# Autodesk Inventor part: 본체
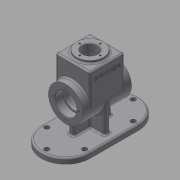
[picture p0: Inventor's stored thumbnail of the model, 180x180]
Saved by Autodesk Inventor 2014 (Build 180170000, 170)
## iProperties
Created: 2019-01
Part Number: 본체
Material: 일반
Document SubType Name: Modeling
Designer: mduedu
Density: 1 g/cm^3
Appearance: 기본값
Author: mduedu
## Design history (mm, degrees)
sketch "스케치1"
  geometry: C1 r 32 at (0, 0); 1 further point
  constraints: 1 centre point, 1 coincident
  dimensions: "d0" = 64 diameter of C1
extrude "돌출1" new body sketch "스케치1" stored distance "d1" = 90; taper "d2" = 0 deg
sketch "스케치2"
  geometry: L1 (0, 32)-(60, 32); L2 (60, 32)-(60, -32); L3 (60, -32)-(0, -32); L4 (0, -32)-(0, 32); C1 r 32 at (0, 0) reference; 2 further points
  constraints: 8 end point, 2 parallel, 1 coincident, 1 horizontal, 1 midpoint, 1 perpendicular, 1 tangent
  dimensions: "d5" = 60 distance between parallel lines of L4 L2
extrude "돌출2" join sketch "스케치2" stored distance "d7" = 64; taper "d8" = 0 deg
sketch "스케치3"
  geometry: C1 r 25 at (32, 32); 1 further point
  constraints: 1 centre point, 1 coincident
  dimensions: "d9" = 50 diameter of C1
extrude "돌출3" join sketch "스케치3" distance "d10" = 5; taper "d11" = 0 deg
sketch "스케치4"
  geometry: L1 (50, 25)-(0, 25); L2 (0, 25)-(0, -25); L3 (0, -25)-(50, -25); L4 (50, -25)-(50, 25); L5 (65, -25)-(65, 25) reference; A1 r 25 centre (0, 0) between (0, 25) and (0, -25); A2 r 25 centre (0, 0) between (0, -25) and (0, 25); 2 further points
  constraints: 8 end point, 4 point on circle, 2 centre point, 2 coincident, 2 parallel, 1 horizontal, 1 midpoint, 1 perpendicular, 1 tangent
  dimensions: "d12" = 50 diameter of A1; "d13" = 15 distance between parallel lines of L4 L5
extrude "돌출4" cut sketch "스케치4" stored distance "d14" = 48; taper "d15" = 0 deg
sketch "스케치5"
  geometry: C1 r 20 at (0, 0); 1 further point
  constraints: 1 centre point, 1 coincident
  dimensions: "d16" = 40 diameter of C1
extrude "돌출5" cut sketch "스케치5" distance "d17" = 15; taper "d18" = 0 deg
sketch "스케치6"
  geometry: C1 r 17 at (0, 0); 1 further point
  constraints: 1 centre point, 1 coincident
  dimensions: "d19" = 34 diameter of C1
extrude "돌출6" cut sketch "스케치6" stored distance "d20" = 15; taper "d21" = 0 deg
fillet "모깎기1" dims "d22" = 0.3
fillet "모깎기2" dims "d23" = 3
fillet "모깎기3" dims "d24" = 3
fillet "모깎기4" dims "d25" = 3
fillet "모깎기5" dims "d26" = 3
fillet "모깎기6" dims "d27" = 3
sketch "스케치7"
  geometry: C1 r 14 at (0, 0); 1 further point
  constraints: 1 centre point, 1 coincident
  dimensions: "d28" = 28 diameter of C1
extrude "돌출7" cut sketch "스케치7" stored distance "d29" = 15; taper "d30" = 0 deg
chamfer "모따기1" distance "d31" = 1; stored, may be unused: second distance "d32" = 2, angle "d33" = 45 deg
chamfer "모따기2" distance "d34" = 1; stored, may be unused: second distance "d35" = 2, angle "d36" = 45 deg
node "작업 평면1"
sketch "스케치8"
  geometry: L1 (45, 45)-(-45, 45); L2 (-45, 45)-(-45, -45); L3 (-45, -45)-(45, -45); L4 (45, -45)-(45, 45); L5 (45, 45)-(-45, -45); L6 (-45, 45)-(45, -45); A1 r 45 centre (45, 0) between (45, -45) and (45, 45); A2 r 45 centre (-45, 0) between (-45, 45) and (-45, -45); A3 r 45 centre (45, 0) between (0, 0) and (45, -45); A4 r 45 centre (45, 0) between (0, 0) and (0, 0); A5 r 45 centre (45, 0) between (45, 45) and (0, 0); A6 r 45 centre (-45, 0) between (0, 0) and (-45, 45); A7 r 45 centre (-45, 0) between (-45, -45) and (0, 0); 1 further point
  constraints: 14 point on circle, 12 end point, 7 centre point, 7 midpoint, 2 parallel, 1 horizontal, 1 perpendicular
  dimensions: "d99" = 90 distance between parallel lines of L1 L3; "d101" = 90 distance between parallel lines of L2 L4
extrude "돌출8" join sketch "스케치8" distance "d41" = 10; taper "d42" = 0 deg
sketch "스케치9"
  geometry: L1 (-35, 5)-(35, 5); L2 (35, 5)-(35, -5); L3 (35, -5)-(-35, -5); L4 (-35, -5)-(-35, 5); 3 further points
  constraints: 8 end point, 2 midpoint, 2 parallel, 1 horizontal, 1 horizontal alignment, 1 perpendicular, 1 vertical alignment
  dimensions: "d52" = 10 distance of L1.end L2.end; "d54" = 70 distance of L1.start L1.end
extrude "돌출9" join sketch "스케치9" stored distance "d50" = 10; taper "d51" = 0 deg
sketch "스케치10"
  geometry: L1 (0, -25)-(47, -25) reference; L2 (50, -22)-(50, -14) reference; L3 (50, -14)-(64, -14) reference; L4 (64, -14)-(65, -15) reference; L5 (65, -15)-(65, -25) reference; L6 (65, -25)-(63, -25) reference; L7 (60, -28)-(60, -29) reference; L8 (57, -32)-(0, -32) reference; L9 (-31.607, -5)-(-55, -5) reference; L10 (-55, -5)-(-55, -45) reference; L11 (-65, -45)-(-65, 45) reference; L12 (-55, 45)-(-55, 5) reference; L13 (-55, 5)-(-31.607, 5) reference; L14 (0, 32)-(57, 32) reference; L15 (60, 29)-(60, 28) reference; L16 (63, 25)-(65, 25) reference; L17 (65, 25)-(65, 15) reference; L18 (65, 15)-(64, 14) reference; L19 (64, 14)-(50, 14) reference; L20 (50, 14)-(50, 22) reference; L21 (47, 25)-(0, 25) reference; L22 (-55, -45)-(-65, -45) reference; L23 (-65, 45)-(-55, 45) reference; L24 (0, 32)-(-55, 32); A1 r 25 centre (0, 0) between (0, 25) and (0, -25) reference; A2 r 3 centre (47, -22) between (47, -25) and (50, -22) reference; A3 r 3 centre (63, -28) between (63, -25) and (60, -28) reference; A4 r 3 centre (57, -29) between (57, -32) and (60, -29) reference; A5 r 32 centre (0, 0) between (-31.607, -5) and (0, -32) reference; A6 r 32 centre (0, 0) between (0, 32) and (-31.607, 5) reference; A7 r 3 centre (57, 29) between (60, 29) and (57, 32) reference; A8 r 3 centre (63, 28) between (60, 28) and (63, 25) reference; A9 r 3 centre (47, 22) between (50, 22) and (47, 25) reference
  constraints: 2 end point, 1 perpendicular, 1 point on line, 1 tangent
feature "리브1" sketch "스케치10" dims "d57" = 1, "d58" = 10, "d59" = 0, "d60" = 0, "d61" = 1, "d62" = 1
fillet "모깎기7" dims "d63" = 3
fillet "모깎기11" dims "d102" = 3
fillet "모깎기8" dims "d64" = 3
sketch "스케치11"
  geometry: L1 (8, -29)-(8, -8) reference; L2 (-8, -8)-(-8, -29) reference; L3 (-32, -8)-(-8, -8) reference; L4 (-38, 2)-(-38, -2) reference; L5 (-8, 8)-(-32, 8) reference; L6 (-8, 29)-(-8, 8) reference; L7 (8, 8)-(8, 29) reference; L8 (32, 8)-(8, 8) reference; L9 (38, -2)-(38, 2) reference; L10 (8, -8)-(32, -8) reference; L11 (-2, -35)-(2, -35) reference; L12 (2, 35)-(-2, 35) reference; L13 (-45, -45)-(45, -45) reference; L14 (45, 45)-(-45, 45) reference; L15 (-45, -35)-(45, -35); L16 (45, 35)-(-45, 35); A1 r 6 centre (-32, -2) between (-38, -2) and (-32, -8) reference; A2 r 6 centre (-32, 2) between (-32, 8) and (-38, 2) reference; A3 r 6 centre (32, 2) between (38, 2) and (32, 8) reference; A4 r 6 centre (32, -2) between (32, -8) and (38, -2) reference; A5 r 6 centre (2, -29) between (2, -35) and (8, -29) reference; A6 r 6 centre (-2, -29) between (-8, -29) and (-2, -35) reference; A7 r 6 centre (-2, 29) between (-2, 35) and (-8, 29) reference; A8 r 6 centre (2, 29) between (8, 29) and (2, 35) reference; A9 r 45 centre (-45, 0) between (-45, 45) and (-45, -45) reference; A10 r 45 centre (45, 0) between (45, -45) and (45, 45) reference; A11 r 35 centre (-45, 0) between (-45, 35) and (-45, -35); A12 r 35 centre (45, 0) between (45, -35) and (45, 35); 7 further points
  constraints: 6 point on circle, 4 coincident, 4 end point, 2 centre point, 3 other
  dimensions: "d103" = 10 distance between parallel lines of L16 L14
hole "구멍1" sketch "스케치11" at (-45, 35), (-80, 0), (-45, -35), (45, -35), (80, 0), (45, 35) diameter "d66" = 9; stored, may be unused: countersink angle "d70" = 90 deg, drill point angle "d72" = 118 deg; dims "d67" = 6, "d68" = 4, "d69" = 2, "d71" = 8
fillet "모깎기10" dims "d73" = 3
sketch "스케치12"
  geometry: L1 (-3, 57)-(-3, 19.596) reference; 2 further points
  constraints: 1 other
  dimensions: "d74" = 32 distance from line of point (29, 45) L1; "d75" = 45 distance of point (29, 45) point (29, 0)
feature "엠보싱1" sketch "스케치12" dims "d12" = 50, "d13" = 15, "d76" = 0.5, "d77" = 0
sketch "스케치13"
  geometry: 4 further points
  constraints: 4 other
hole "구멍2" sketch "스케치13" at (-25, 0), (0, -25), (25, 0), (0, 25) diameter "d78" = 3.242; stored, may be unused: countersink angle "d82" = 90 deg, drill point angle "d84" = 120 deg; dims "d79" = 7, "d80" = 4, "d81" = 2, "d83" = 9
sketch "스케치14"
  geometry: 4 further points
  constraints: 4 other
hole "구멍3" sketch "스케치14" at (-25, 0), (0, -25), (25, 0), (0, 25) diameter "d85" = 3.242; stored, may be unused: countersink angle "d89" = 90 deg, drill point angle "d91" = 120 deg; dims "d86" = 7, "d87" = 4, "d88" = 2, "d90" = 9
sketch "스케치15"
  geometry: 4 further points
  constraints: 4 other
hole "구멍4" sketch "스케치15" at (0, -19), (19, 0), (0, 19), (-19, 0) diameter "d92" = 3.242; stored, may be unused: countersink angle "d96" = 90 deg, drill point angle "d98" = 120 deg; dims "d93" = 8, "d94" = 4, "d95" = 2, "d97" = 10
node "솔리드1"
mirror "대칭1"
mirror "대칭2"
node "투영된 루프1"
node "투영된 루프2"
node "절단 모서리 투영1"
node "절단 모서리 투영2"
other parameters: "d37" = -65
